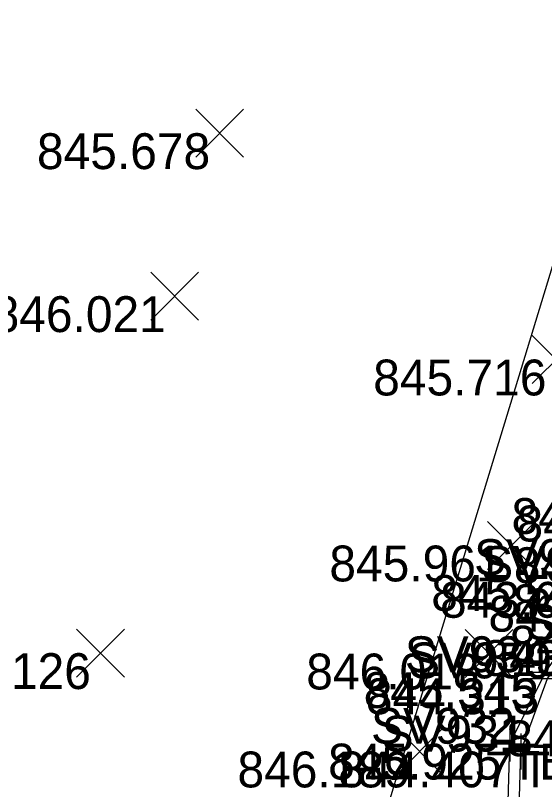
# Model space of a CAD drawing. Extents: x 2228183 to 2230895, y 679226 to 682223.
# Drawn here: x 2228365.44 to 2228380.2, y 680600.58 to 680622.17 of the extents above; entities that cross this region are included whole.
import ezdxf

# ---------------------------------------------------------------- set-up
doc = ezdxf.new("R2010")
doc.units = 0
for name, color, linetype in [('SC_Scratch1', 7, 'Continuous'), ('SV_P_Control_Cells_Set', 7, 'Continuous'), ('SV_X_Random_Point', 7, 'Continuous'), ('SV_X_Shot_Marker', 7, 'Continuous'), ('SV_X_Text_Comment', 7, 'Continuous'), ('SV_X_Toe_of_Slope', 7, 'Continuous'), ('SV_X_Top_of_Bank', 7, 'Continuous'), ('VG_X_Tree_Line_Rt', 7, 'Continuous')]:
    doc.layers.add(name, color=color, linetype=linetype)

msp = doc.modelspace()

# ---------------------------------------------------------------- linework, layer by layer
at = {"layer": 'SV_X_Random_Point'}
for p, q in [((2228370.467, 680618.221), (2228371.801, 680619.556)), ((2228370.467, 680619.556), (2228371.801, 680618.221)), ((2228369.211, 680613.675), (2228370.545, 680615.01)), ((2228369.211, 680615.01), (2228370.545, 680613.675)), ((2228379.853, 680611.907), (2228381.187, 680613.242)), ((2228379.853, 680613.242), (2228381.187, 680611.907)), ((2228378.607, 680606.719), (2228379.941, 680608.054)), ((2228378.607, 680608.054), (2228379.941, 680606.719)), ((2228367.142, 680603.716), (2228368.476, 680605.051)), ((2228367.142, 680605.051), (2228368.476, 680603.716)), ((2228377.981, 680603.705), (2228379.315, 680605.04)), ((2228377.981, 680605.04), (2228379.315, 680603.705)), ((2228376.045, 680600.972), (2228377.379, 680602.307)), ((2228376.045, 680602.307), (2228377.379, 680600.972))]:
    msp.add_line(p, q, dxfattribs=at)
at = {"layer": 'SV_X_Shot_Marker'}
for p, q in [((2228379.719, 680603.854), (2228380.719, 680603.854)), ((2228379.775, 680603.681), (2228380.775, 680603.681)), ((2228379.228, 680602.359), (2228379.228, 680601.359)), ((2228379.535, 680602.141), (2228379.535, 680601.141)), ((2228378.728, 680601.859), (2228379.728, 680601.859)), ((2228379.228, 680601.859), (2228379.228, 680601.859)), ((2228379.035, 680601.641), (2228380.035, 680601.641)), ((2228379.535, 680601.641), (2228379.535, 680601.641))]:
    msp.add_line(p, q, dxfattribs=at)
at = {"layer": 'SV_X_Toe_of_Slope'}
msp.add_lwpolyline([(2228382.721, 680589.768), (2228382.394, 680591.275), (2228381.578, 680592.261), (2228380.377, 680592.786), (2228380.017, 680594.252), (2228378.91, 680596.888), (2228379.463, 680599.095), (2228379.535, 680601.641), (2228380.275, 680603.681), (2228382.344, 680606.372), (2228384.513, 680608.501), (2228385.491, 680609.618), (2228386.937, 680611.065), (2228389.519, 680612.631), (2228391.086, 680613.13), (2228391.743, 680613.004)], dxfattribs=at)
at = {"layer": 'SV_X_Top_of_Bank'}
msp.add_lwpolyline([(2228384.257, 680589.104), (2228383.744, 680587.391), (2228381.097, 680587.303), (2228381.365, 680589.869), (2228380.769, 680591.835), (2228379.012, 680592.513), (2228379.324, 680594.144), (2228378.396, 680597.117), (2228379.152, 680599.266), (2228379.228, 680601.859), (2228380.219, 680603.854), (2228382.1, 680606.564), (2228384.378, 680608.711), (2228386.687, 680611.375), (2228389.279, 680612.996), (2228390.948, 680613.613), (2228391.856, 680613.495)], dxfattribs=at)
at = {"layer": 'VG_X_Tree_Line_Rt'}
msp.add_lwpolyline([(2228410.452, 680773.345), (2228402.142, 680728.483), (2228403.602, 680691.208), (2228374.606, 680596.133), (2228370.969, 680582.119), (2228367.614, 680567.008), (2228346.3, 680486.661), (2228340.655, 680455.186), (2228334.048, 680383.235)], dxfattribs=at)

# ---------------------------------------------------------------- texts
at = {"layer": 'SC_Scratch1'}
for s, p in [('845.678', (2228366.034, 680617.888)), ('846.021', (2228364.796, 680613.342)), ('845.716', (2228375.416, 680611.574)), ('845.636', (2228379.274, 680607.711)), ('843.298', (2228379.413, 680607.501)), ('845.961', (2228374.192, 680606.386)), ('843.147', (2228379.34, 680606.337)), ('845.573', (2228377.036, 680605.564)), ('843.653', (2228377.28, 680605.372)), ('843.255', (2228379.312, 680605.306)), ('843.292', (2228378.63, 680604.985)), ('843.325', (2228379.22, 680604.149)), ('843.519', (2228378.47, 680603.75)), ('846.126', (2228362.705, 680603.383)), ('846.018', (2228373.548, 680603.372)), ('845.545', (2228375.149, 680602.854)), ('844.313', (2228375.211, 680602.681)), ('843.912', (2228379.128, 680601.508)), ('845.925', (2228374.158, 680600.859)), ('846.189', (2228371.628, 680600.639)), ('844.407', (2228374.439, 680600.641))]:
    msp.add_text(s, height=1, dxfattribs=at).set_placement(p)
at = {"layer": 'SV_P_Control_Cells_Set'}
for s, p in [('SV935', (2228378.23, 680606.564)), ('SV960', (2228378.43, 680606.372)), ('SV789', (2228379.67, 680604.75)), ('SV934', (2228376.297, 680603.854)), ('SV959', (2228376.391, 680603.681)), ('SV932', (2228375.355, 680601.859)), ('SV931', (2228375.653, 680601.641))]:
    msp.add_text(s, height=1, dxfattribs=at).set_placement(p)
at = {"layer": 'SV_X_Text_Comment'}
for s, p in [('TB', (2228379.228, 680600.859)), ('TSL1', (2228379.535, 680600.641))]:
    msp.add_text(s, height=1, dxfattribs=at).set_placement(p)

doc.saveas('drawing.dxf')
